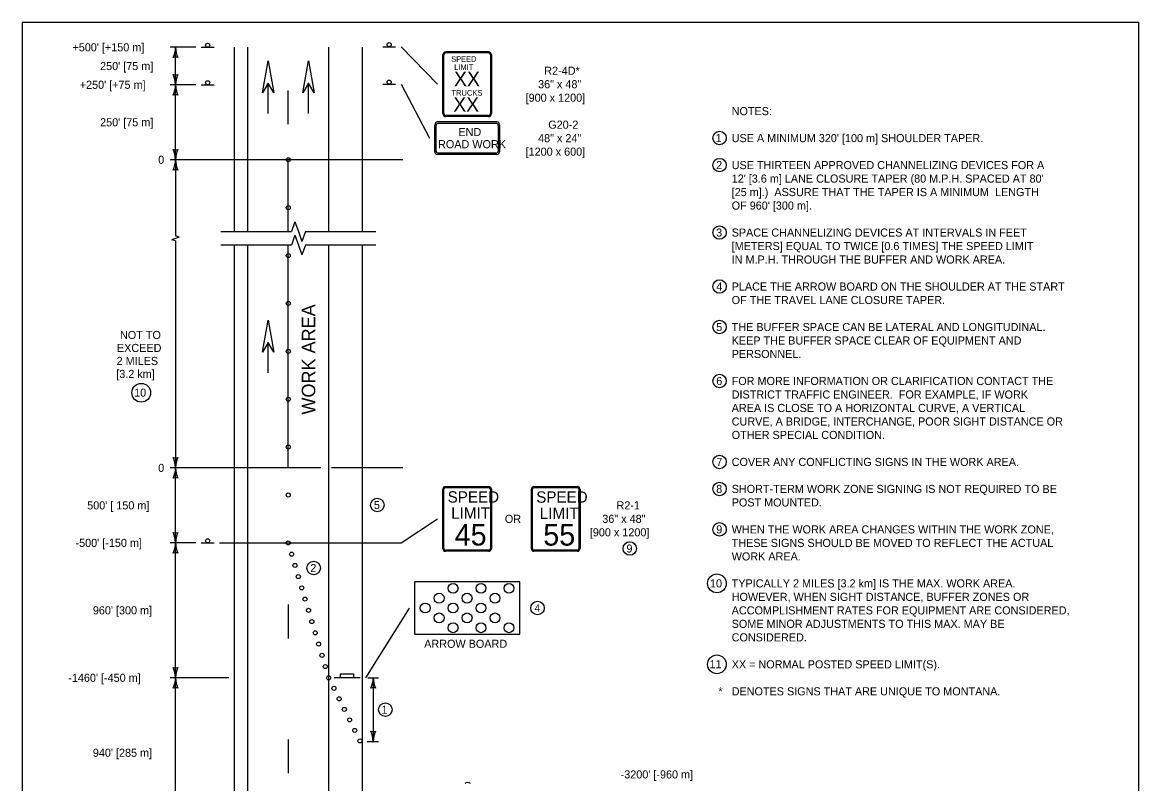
# Model space of a CAD drawing. Extents: x 49991.4 to 50021, y 49987.6 to 50011.4.
# Drawn here: x 50000.34 to 50008.61, y 50005.62 to 50011.26 of the extents above; entities that cross this region are included whole.
import ezdxf

# ---------------------------------------------------------------- set-up
doc = ezdxf.new("R2010")
doc.units = 0
for name, color, linetype in [('Level 1', 7, 'Continuous'), ('Level 2', 7, 'Continuous'), ('Level 25', 7, 'Continuous'), ('Level 3', 7, 'Continuous'), ('Level 6', 7, 'Continuous'), ('S_BOT_RW_TTL_Sheet_No_DF', 7, 'Continuous')]:
    doc.layers.add(name, color=color, linetype=linetype)

msp = doc.modelspace()

# ---------------------------------------------------------------- linework, layer by layer
at = {"layer": 'Level 1'}
for p, q in [((50001.6621, 50011.0778), (50001.7581, 50011.0778)), ((50001.908, 50009.7117), (50001.908, 50011.0778)), ((50002.008, 50009.7117), (50002.008, 50011.0778)), ((50002.608, 50009.7117), (50002.608, 50011.0778)), ((50002.858, 50009.7117), (50002.858, 50011.0778)), ((50003.0081, 50011.082), (50003.1041, 50011.082)), ((50003.7918, 50011.0442), (50003.4768, 50011.0442)), ((50003.4543, 50010.5868), (50003.4543, 50011.0217)), ((50003.4619, 50010.5868), (50003.4619, 50011.0217)), ((50003.7918, 50011.0366), (50003.4768, 50011.0366)), ((50003.8067, 50011.0217), (50003.8067, 50010.5868)), ((50003.8143, 50011.0217), (50003.8143, 50010.5868)), ((50001.6621, 50010.8001), (50001.7581, 50010.8001)), ((50002.158, 50010.5866), (50002.158, 50010.8125)), ((50002.1583, 50010.5866), (50002.1583, 50010.8125)), ((50002.458, 50010.5866), (50002.458, 50010.8125)), ((50002.4583, 50010.5866), (50002.4583, 50010.8125)), ((50003.0081, 50010.8043), (50003.1041, 50010.8043)), ((50003.6378, 50010.8465), (50003.6378, 50010.8465)), ((50002.308, 50010.5073), (50002.308, 50010.7572)), ((50003.7918, 50010.5719), (50003.4768, 50010.5719)), ((50003.7918, 50010.5643), (50003.4768, 50010.5643)), ((50003.3945, 50010.3043), (50003.3945, 50010.5043)), ((50003.4045, 50010.3093), (50003.4045, 50010.4993)), ((50003.8545, 50010.5243), (50003.4145, 50010.5243)), ((50003.8495, 50010.5143), (50003.4195, 50010.5143)), ((50003.8645, 50010.4993), (50003.8645, 50010.3093)), ((50003.8745, 50010.5043), (50003.8745, 50010.3043)), ((50003.8495, 50010.2943), (50003.4195, 50010.2943)), ((50002.3079, 50009.7117), (50002.308, 50010.2444)), ((50003.8545, 50010.2843), (50003.4145, 50010.2843)), ((50001.908, 50000.5011), (50001.908, 50009.6117)), ((50002.008, 50000.5011), (50002.008, 50009.6117)), ((50002.3075, 50007.9608), (50002.3079, 50009.6117)), ((50002.608, 50000.5032), (50002.608, 50009.6117)), ((50002.858, 50000.5011), (50002.858, 50009.6117)), ((50002.158, 50008.6649), (50002.158, 50008.8907)), ((50002.1583, 50008.6649), (50002.1583, 50008.8907)), ((50003.4729, 50007.8233), (50003.7954, 50007.8233)), ((50003.4729, 50007.8153), (50003.7954, 50007.8153)), ((50004.1302, 50007.8233), (50004.4527, 50007.8233)), ((50004.1302, 50007.8153), (50004.4527, 50007.8153)), ((50003.4541, 50007.3633), (50003.4541, 50007.8033)), ((50003.4616, 50007.3633), (50003.4616, 50007.8033)), ((50003.8066, 50007.8033), (50003.8066, 50007.3633)), ((50003.8141, 50007.8033), (50003.8141, 50007.3633)), ((50004.1114, 50007.3633), (50004.1114, 50007.8033)), ((50004.1189, 50007.3633), (50004.1189, 50007.8033)), ((50004.4639, 50007.8033), (50004.4639, 50007.3633)), ((50004.4714, 50007.8033), (50004.4714, 50007.3633)), ((50001.6621, 50007.4053), (50001.7581, 50007.4053)), ((50003.7954, 50007.3513), (50003.4729, 50007.3513)), ((50003.7954, 50007.3433), (50003.4729, 50007.3433)), ((50004.4527, 50007.3513), (50004.1302, 50007.3513)), ((50004.4527, 50007.3433), (50004.1302, 50007.3433)), ((50002.308, 50006.9475), (50002.308, 50006.6976)), ((50002.8401, 50006.4052), (50002.6481, 50006.4052)), ((50002.308, 50005.9476), (50002.308, 50005.6977))]:
    msp.add_line(p, q, dxfattribs=at)
for points in [[(50008.6146, 50011.2628), (50000.3356, 50011.2628), (50000.3356, 50000.0624), (50008.6146, 50000.0624)], [(50002.1163, 50010.7402), (50002.158, 50010.9767), (50002.1999, 50010.7402), (50002.158, 50010.8124)], [(50002.4163, 50010.7402), (50002.458, 50010.9767), (50002.4999, 50010.7402), (50002.458, 50010.8124)], [(50002.1163, 50008.8185), (50002.158, 50009.0549), (50002.1999, 50008.8185), (50002.158, 50008.8907)], [(50003.2443, 50006.7273), (50004.024, 50006.7273), (50004.024, 50007.1173), (50003.2443, 50007.1173)], [(50003.2443, 50006.7273), (50004.024, 50006.7273), (50004.024, 50007.1173), (50003.2443, 50007.1173)], [(50002.6961, 50006.4356), (50002.7921, 50006.4356), (50002.7921, 50006.4052), (50002.6961, 50006.4052)]]:
    msp.add_lwpolyline(points, close=True, dxfattribs=at)
for centre, radius in [((50001.7101, 50011.093), 0.0152), ((50003.0561, 50011.0972), 0.0152), ((50001.7101, 50010.8153), 0.0152), ((50003.0561, 50010.8196), 0.0152), ((50002.308, 50010.2443), 0.015), ((50002.308, 50009.8894), 0.015), ((50002.308, 50009.5345), 0.015), ((50002.308, 50009.1796), 0.015), ((50002.308, 50008.8247), 0.015), ((50002.308, 50008.4698), 0.015), ((50002.308, 50008.1149), 0.015), ((50002.308, 50007.76), 0.015), ((50001.71, 50007.4204), 0.0152), ((50002.3073, 50007.4049), 0.015), ((50002.3324, 50007.3216), 0.015), ((50002.3574, 50007.2383), 0.015), ((50002.3825, 50007.1549), 0.015), ((50002.4075, 50007.0716), 0.015), ((50003.5304, 50007.0683), 0.0366), ((50003.5304, 50007.0683), 0.0366), ((50003.7375, 50007.0683), 0.0366), ((50003.7375, 50007.0683), 0.0366), ((50003.9446, 50007.0683), 0.0366), ((50003.9446, 50007.0683), 0.0366), ((50002.4326, 50006.9883), 0.015), ((50003.4268, 50006.9952), 0.0366), ((50003.4268, 50006.9952), 0.0366), ((50003.6339, 50006.9952), 0.0366), ((50003.6339, 50006.9952), 0.0366), ((50003.8411, 50006.9952), 0.0366), ((50003.8411, 50006.9952), 0.0366), ((50002.4577, 50006.905), 0.015), ((50003.3233, 50006.9221), 0.0366), ((50003.3233, 50006.9221), 0.0366), ((50003.5304, 50006.9221), 0.0366), ((50003.5304, 50006.9221), 0.0366), ((50003.7375, 50006.9221), 0.0366), ((50003.7375, 50006.9221), 0.0366), ((50002.4827, 50006.8217), 0.015), ((50003.4268, 50006.849), 0.0366), ((50003.4268, 50006.849), 0.0366), ((50003.6339, 50006.849), 0.0366), ((50003.6339, 50006.849), 0.0366), ((50003.8411, 50006.849), 0.0366), ((50003.8411, 50006.849), 0.0366), ((50002.5078, 50006.7384), 0.015), ((50003.5304, 50006.7759), 0.0366), ((50003.5304, 50006.7759), 0.0366), ((50003.7375, 50006.7759), 0.0366), ((50003.7375, 50006.7759), 0.0366), ((50003.9446, 50006.7759), 0.0366), ((50003.9446, 50006.7759), 0.0366), ((50002.5328, 50006.6551), 0.015), ((50002.5579, 50006.5717), 0.015), ((50002.5829, 50006.4884), 0.015), ((50002.608, 50006.4051), 0.015), ((50002.6466, 50006.3272), 0.015), ((50002.6852, 50006.2492), 0.015), ((50002.7238, 50006.1712), 0.015), ((50002.7625, 50006.0933), 0.015), ((50002.8011, 50006.0153), 0.015), ((50002.8397, 50005.9374), 0.015)]:
    msp.add_circle(centre, radius, dxfattribs=at)
for centre, radius, start, end in [((50003.4768, 50011.0217), 0.0225, 90, 180), ((50003.7918, 50011.0217), 0.0225, 0, 90), ((50003.4768, 50011.0217), 0.0149, 90, 180), ((50003.7918, 50011.0217), 0.0149, 0, 90), ((50003.4768, 50010.5868), 0.0225, 180, 270), ((50003.4768, 50010.5868), 0.0149, 180, 270), ((50003.7918, 50010.5868), 0.0225, 270, 0), ((50003.7918, 50010.5868), 0.0149, 270, 0), ((50003.4145, 50010.5043), 0.02, 90, 180), ((50003.4195, 50010.4993), 0.015, 90, 180), ((50003.8495, 50010.4993), 0.015, 0, 90), ((50003.8545, 50010.5043), 0.02, 0, 90), ((50003.4143, 50010.3043), 0.02, 180, 270), ((50003.4195, 50010.3093), 0.015, 180, 270), ((50003.8495, 50010.3093), 0.015, 270, 0), ((50003.8543, 50010.3043), 0.02, 270, 360)]:
    msp.add_arc(centre, radius, start, end, dxfattribs=at)
for centre, major_axis, start_param, end_param in [((50003.4727, 50007.8032), (0, -0.02), 3.141593, 4.712389), ((50003.4727, 50007.8032), (0, -0.012), 3.141593, 4.712389), ((50003.7952, 50007.8032), (0, 0.02), 4.712389, 6.283185), ((50003.7952, 50007.8032), (0, 0.012), 4.712389, 6.283185), ((50004.13, 50007.8031), (0, -0.02), 3.141593, 4.712389), ((50004.13, 50007.8031), (0, -0.012), 3.141593, 4.712389), ((50004.4525, 50007.8031), (0, 0.02), 4.712389, 6.283185), ((50004.4525, 50007.8031), (0, 0.012), 4.712389, 6.283185), ((50003.4727, 50007.3632), (0, -0.02), 4.712389, 6.283185), ((50003.4727, 50007.3632), (0, -0.012), 4.712389, 6.283185), ((50003.7952, 50007.3632), (0, 0.02), 3.141593, 4.712389), ((50003.7952, 50007.3632), (0, 0.012), 3.141593, 4.712389), ((50004.13, 50007.3631), (0, -0.02), 4.712389, 6.283185), ((50004.13, 50007.3631), (0, -0.012), 4.712389, 6.283185), ((50004.4525, 50007.3631), (0, 0.02), 3.141593, 4.712389), ((50004.4525, 50007.3631), (0, 0.012), 3.141593, 4.712389)]:
    msp.add_ellipse(centre, major_axis=major_axis, ratio=0.9375, start_param=start_param, end_param=end_param, dxfattribs=at)
at = {"layer": 'Level 2'}
for centre, radius in [((50005.5063, 50010.4054), 0.05), ((50005.5063, 50010.2049), 0.05), ((50005.5063, 50009.7049), 0.05), ((50005.5063, 50009.3049), 0.05), ((50005.5063, 50009.0049), 0.05), ((50005.5063, 50008.6049), 0.05), ((50001.2176, 50008.5178), 0.0695), ((50005.5063, 50008.0049), 0.05), ((50005.5063, 50007.8049), 0.05), ((50002.968, 50007.6856), 0.05), ((50005.5063, 50007.5049), 0.05), ((50004.8406, 50007.3633), 0.05), ((50002.4964, 50007.2186), 0.05), ((50005.4868, 50007.1049), 0.0695), ((50004.1561, 50006.9221), 0.05), ((50005.4868, 50006.5049), 0.0695), ((50003.028, 50006.1689), 0.05)]:
    msp.add_circle(centre, radius, dxfattribs=at)
at = {"layer": 'Level 25'}
msp.add_arc((50003.6385, 50005.5988), 0.0308, 45.00007, 134.99993, dxfattribs=at)
at = {"layer": 'Level 3'}
for p, q in [((50001.622, 50011.0778), (50001.432, 50011.0778)), ((50001.472, 50010.8), (50001.472, 50011.0778)), ((50003.144, 50011.082), (50003.4143, 50010.8043)), ((50001.622, 50010.8), (50001.432, 50010.8)), ((50001.472, 50010.5222), (50001.472, 50010.8)), ((50001.472, 50010.2444), (50001.472, 50010.5222)), ((50003.158, 50010.2444), (50001.432, 50010.2444)), ((50001.472, 50010.2444), (50001.472, 50009.6811)), ((50001.472, 50009.6617), (50001.4446, 50009.652)), ((50001.472, 50009.6423), (50001.4446, 50009.652)), ((50001.4994, 50009.6714), (50001.472, 50009.6811)), ((50001.4994, 50009.6714), (50001.472, 50009.6617)), ((50001.472, 50009.6423), (50001.472, 50007.9608)), ((50002.5491, 50007.9608), (50001.432, 50007.9608)), ((50001.472, 50007.683), (50001.472, 50007.9608)), ((50003.158, 50007.9608), (50002.6291, 50007.9608)), ((50001.472, 50007.4052), (50001.472, 50007.683)), ((50003.1441, 50007.4053), (50003.4141, 50007.5833)), ((50001.622, 50007.4052), (50001.432, 50007.4052)), ((50001.472, 50006.4052), (50001.472, 50007.4052)), ((50001.7981, 50007.4053), (50003.1441, 50007.4053)), ((50003.2043, 50006.9223), (50002.8801, 50006.4052)), ((50001.868, 50006.4052), (50001.432, 50006.4052)), ((50001.472, 50005.2941), (50001.472, 50006.4052)), ((50002.898, 50006.4052), (50002.978, 50006.4052)), ((50002.938, 50006.4052), (50002.938, 50005.9326)), ((50002.8939, 50005.9326), (50002.978, 50005.9326))]:
    msp.add_line(p, q, dxfattribs=at)
for centre, radius, start, end in [((50001.2499, 50011.0869), 0.2223, 337.45601, 357.63952), ((50001.7047, 50011.0892), 0.233, 182.82731, 202.07716), ((50001.472, 50010.9495), 0.0548, 72.13882, 107.86118), ((50001.472, 50010.9282), 0.0548, 252.13882, 287.86118), ((50001.2393, 50010.7885), 0.233, 2.82731, 22.07716), ((50001.6942, 50010.7908), 0.2223, 157.45601, 177.63952), ((50001.2499, 50010.8091), 0.2223, 337.45601, 357.63952), ((50001.7047, 50010.8114), 0.233, 182.82731, 202.07716), ((50001.472, 50010.6717), 0.0548, 72.13882, 107.86118), ((50001.472, 50010.3726), 0.0548, 252.13882, 287.86118), ((50001.2393, 50010.2329), 0.233, 2.82731, 22.07716), ((50001.6942, 50010.2352), 0.2223, 157.45601, 177.63952), ((50001.2499, 50010.2535), 0.2223, 337.45601, 357.63952), ((50001.7047, 50010.2558), 0.233, 182.82731, 202.07716), ((50001.472, 50010.1161), 0.0548, 72.13882, 107.86118), ((50001.472, 50008.089), 0.0548, 252.13882, 287.86118), ((50001.2393, 50007.9493), 0.233, 2.82731, 22.07716), ((50001.6942, 50007.9517), 0.2223, 157.45601, 177.63952), ((50001.2499, 50007.97), 0.2223, 337.45601, 357.63952), ((50001.7047, 50007.9723), 0.233, 182.82731, 202.07716), ((50001.472, 50007.8326), 0.0548, 72.13882, 107.86118), ((50001.472, 50007.5334), 0.0548, 252.13882, 287.86118), ((50001.2393, 50007.3937), 0.233, 2.82731, 22.07716), ((50001.6942, 50007.3961), 0.2223, 157.45601, 177.63952), ((50001.2499, 50007.4144), 0.2223, 337.45601, 357.63952), ((50001.7047, 50007.4167), 0.233, 182.82731, 202.07716), ((50001.472, 50007.277), 0.0548, 72.13882, 107.86118), ((50001.472, 50006.5334), 0.0548, 252.13882, 287.86118), ((50001.2393, 50006.3937), 0.233, 2.82731, 22.07716), ((50001.2499, 50006.4144), 0.2223, 337.45601, 357.63952), ((50001.6942, 50006.3961), 0.2223, 157.45601, 177.63952), ((50001.7047, 50006.4167), 0.233, 182.82731, 202.07716), ((50002.7159, 50006.4144), 0.2223, 337.45601, 357.63952), ((50003.1707, 50006.4167), 0.233, 182.82731, 202.07716), ((50001.472, 50006.277), 0.0548, 72.13882, 107.86118), ((50002.938, 50006.277), 0.0548, 72.13882, 107.86118), ((50002.938, 50006.0608), 0.0548, 252.13882, 287.86118), ((50002.7053, 50005.9211), 0.233, 2.82731, 22.07716), ((50003.1602, 50005.9234), 0.2223, 157.45601, 177.63952)]:
    msp.add_arc(centre, radius, start, end, dxfattribs=at)
at = {"layer": 'Level 6'}
for p, q in [((50002.3572, 50009.7848), (50002.3313, 50009.7117)), ((50002.3572, 50009.7848), (50002.3831, 50009.7117)), ((50001.8081, 50009.7117), (50002.3313, 50009.7117)), ((50002.3572, 50009.6848), (50002.3313, 50009.6117)), ((50002.3572, 50009.6848), (50002.3831, 50009.6117)), ((50002.3831, 50009.7117), (50002.409, 50009.6386)), ((50002.4349, 50009.7117), (50002.409, 50009.6386)), ((50002.4349, 50009.7117), (50002.9581, 50009.7117)), ((50002.3313, 50009.6117), (50001.8081, 50009.6117)), ((50002.3831, 50009.6117), (50002.409, 50009.5386)), ((50002.4349, 50009.6117), (50002.409, 50009.5386)), ((50002.9581, 50009.6117), (50002.4349, 50009.6117))]:
    msp.add_line(p, q, dxfattribs=at)
at = {"layer": 'S_BOT_RW_TTL_Sheet_No_DF'}
msp.add_line((50003.144, 50010.8043), (50003.3545, 50010.4043), dxfattribs=at)

# ---------------------------------------------------------------- texts
at = {"layer": 'Level 1'}
for s, height, p in [('SPEED', 0.04121, (50003.5166, 50010.9701)), ('XX', 0.10831, (50003.5366, 50010.7896)), ('LIMIT', 0.04162, (50003.5384, 50010.9107)), ('TRUCKS', 0.04183, (50003.5182, 50010.7194)), ('XX', 0.10679, (50003.5321, 50010.6013)), ('END', 0.06, (50003.5695, 50010.4198)), ('ROAD WORK', 0.06, (50003.4187, 50010.3298)), ('SPEED', 0.0841, (50003.4899, 50007.7035)), ('SPEED', 0.0841, (50004.1469, 50007.7028)), ('LIMIT', 0.0841, (50003.5165, 50007.5835)), ('LIMIT', 0.0841, (50004.1735, 50007.5828)), ('45', 0.15912, (50003.542, 50007.3856)), ('55', 0.15912, (50004.199, 50007.3849))]:
    msp.add_text(s, height=height, dxfattribs=at).set_placement(p)
at = {"layer": 'Level 2'}
for s, height, p in [("+500' [+150 m]", 0.06, (50000.7074, 50011.0478)), ("250' [75 m]", 0.06, (50000.9125, 50010.9089)), ('R2-4D*', 0.06, (50004.2062, 50010.8743)), ("+250' [+75 m]", 0.06, (50000.7613, 50010.77)), ('36" x 48"', 0.06, (50004.1607, 50010.7743)), ('[900 x 1200]', 0.06, (50004.0682, 50010.6743)), ('NOTES:', 0.06, (50005.5963, 50010.5749)), ("250' [75 m]", 0.06, (50000.9125, 50010.4922)), ('G20-2', 0.06, (50004.2359, 50010.4744)), ('48" x 24"', 0.06, (50004.1607, 50010.3744)), ('1', 0.06, (50005.4774, 50010.3754)), ("USE A MINIMUM 320' [100 m] SHOULDER TAPER.", 0.06, (50005.5963, 50010.3749)), ('[1200 x 600]', 0.06, (50004.0682, 50010.2744)), ('0', 0.06, (50001.3432, 50010.2144)), ('2', 0.06, (50005.4811, 50010.1749)), ('USE THIRTEEN APPROVED CHANNELIZING DEVICES FOR A ', 0.06, (50005.5963, 50010.1749)), ("12' [3.6 m] LANE CLOSURE TAPER (80 M.P.H. SPACED AT 80' ", 0.06, (50005.5963, 50010.0749)), ('[25 m].)  ASSURE THAT THE TAPER IS A MINIMUM  LENGTH ', 0.06, (50005.5963, 50009.9749)), ("OF 960' [300 m]. ", 0.06, (50005.5963, 50009.8749)), ('3', 0.06, (50005.4811, 50009.6749)), ('SPACE CHANNELIZING DEVICES AT INTERVALS IN FEET', 0.06, (50005.5963, 50009.6749)), ('[METERS] EQUAL TO TWICE [0.6 TIMES] THE SPEED LIMIT ', 0.06, (50005.5963, 50009.5749)), ('IN M.P.H. THROUGH THE BUFFER AND WORK AREA.', 0.06, (50005.5963, 50009.4749)), ('4', 0.06, (50005.4823, 50009.2749)), ('PLACE THE ARROW BOARD ON THE SHOULDER AT THE START ', 0.06, (50005.5963, 50009.2749)), ('OF THE TRAVEL LANE CLOSURE TAPER.', 0.06, (50005.5963, 50009.1749)), ('NOT TO', 0.06, (50001.0601, 50008.9159)), ('5', 0.06, (50005.4814, 50008.9749)), ('THE BUFFER SPACE CAN BE LATERAL AND LONGITUDINAL. ', 0.06, (50005.5963, 50008.9749)), ('KEEP THE BUFFER SPACE CLEAR OF EQUIPMENT AND ', 0.06, (50005.5963, 50008.8749)), ('EXCEED', 0.06, (50001.0372, 50008.8197)), ('PERSONNEL.', 0.06, (50005.5963, 50008.7749)), ('2 MILES', 0.06, (50001.0349, 50008.7235)), ('[3.2 km]', 0.06, (50001.0323, 50008.6273)), ('6', 0.06, (50005.4818, 50008.5749)), ('FOR MORE INFORMATION OR CLARIFICATION CONTACT THE ', 0.06, (50005.5963, 50008.5749)), ('10', 0.06, (50001.1649, 50008.4883)), ('DISTRICT TRAFFIC ENGINEER.  FOR EXAMPLE, IF WORK ', 0.06, (50005.5963, 50008.4749)), ('AREA IS CLOSE TO A HORIZONTAL CURVE, A VERTICAL ', 0.06, (50005.5963, 50008.3749)), ('CURVE, A BRIDGE, INTERCHANGE, POOR SIGHT DISTANCE OR ', 0.06, (50005.5963, 50008.2749)), ('OTHER SPECIAL CONDITION.', 0.06, (50005.5963, 50008.1749)), ('0', 0.06, (50001.3432, 50007.9308)), ('7', 0.06, (50005.4825, 50007.9749)), ('COVER ANY CONFLICTING SIGNS IN THE WORK AREA.', 0.06, (50005.5963, 50007.9749)), ('8', 0.06, (50005.4813, 50007.7749)), ('SHORT-TERM WORK ZONE SIGNING IS NOT REQUIRED TO BE ', 0.06, (50005.5963, 50007.7749)), ('POST MOUNTED.', 0.06, (50005.5963, 50007.6749)), ("500' [ 150 m]", 0.06, (50000.8166, 50007.653)), ('5', 0.06, (50002.9431, 50007.6556)), ('R2-1', 0.06, (50004.7424, 50007.6533)), ('OR', 0.06, (50003.9141, 50007.5533)), ('36" x 48"', 0.06, (50004.6368, 50007.5533)), ('[900 x 1200]', 0.06, (50004.5443, 50007.4533)), ('9', 0.06, (50005.4818, 50007.4749)), ('WHEN THE WORK AREA CHANGES WITHIN THE WORK ZONE, ', 0.06, (50005.5963, 50007.4749)), ("-500' [-150 m]", 0.06, (50000.7301, 50007.3752)), ('THESE SIGNS SHOULD BE MOVED TO REFLECT THE ACTUAL ', 0.06, (50005.5963, 50007.3749)), ('9', 0.06, (50004.816, 50007.3333)), ('WORK AREA.', 0.06, (50005.5963, 50007.2749)), ('2', 0.06, (50002.4712, 50007.1886)), ('10', 0.06, (50005.4355, 50007.0749)), ('TYPICALLY 2 MILES [3.2 km] IS THE MAX. WORK AREA.  ', 0.06, (50005.5963, 50007.0749)), ('HOWEVER, WHEN SIGHT DISTANCE, BUFFER ZONES OR ', 0.06, (50005.5963, 50006.9749)), ("960' [300 m]", 0.06, (50000.8587, 50006.8753)), ('4', 0.054, (50004.1345, 50006.8951)), ('ACCOMPLISHMENT RATES FOR EQUIPMENT ARE CONSIDERED, ', 0.06, (50005.5963, 50006.8749)), ('SOME MINOR ADJUSTMENTS TO THIS MAX. MAY BE ', 0.06, (50005.5963, 50006.7749)), ('CONSIDERED.', 0.06, (50005.5963, 50006.6749)), ('ARROW BOARD', 0.06, (50003.3159, 50006.6273)), ('11', 0.06, (50005.4317, 50006.4756)), ('XX = NORMAL POSTED SPEED LIMIT(S).', 0.06, (50005.5963, 50006.4749)), ("-1460' [-450 m]", 0.06, (50000.6762, 50006.3752)), ('*', 0.06, (50005.4977, 50006.2749)), ('DENOTES SIGNS THAT ARE UNIQUE TO MONTANA. ', 0.06, (50005.5963, 50006.2749)), ('1', 0.06, (50002.9991, 50006.1389)), ("940' [285 m]", 0.06, (50000.8587, 50005.8197)), ("-3200' [-960 m]", 0.06, (50004.7727, 50005.6591))]:
    msp.add_text(s, height=height, dxfattribs=at).set_placement(p)
msp.add_text('WORK AREA', height=0.1, rotation=90, dxfattribs=at).set_placement((50002.5081, 50008.3558))

doc.saveas('drawing.dxf')
